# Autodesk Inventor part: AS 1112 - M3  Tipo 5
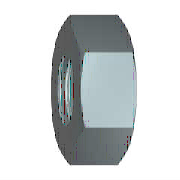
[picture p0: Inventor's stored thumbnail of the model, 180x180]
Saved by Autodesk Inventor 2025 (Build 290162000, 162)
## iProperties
Created: 2024-01
Part Number: AS 1112 - M3  Tipo 5
Material: Acciaio, Dolce
Description: Dadi esagonali metrici ISO, inclusi dadi sottili, dadi con intaglio e dadi a corona
Document SubType Name: Modeling
Standard: AS 1112
Designer: R5800u
Standards Organization: AS
Language: it-IT
Size Designation: M3  Tipo 5
Categories: <MemberInstance><Categories><Category DisplayName="Elementi di fissaggio" InternalName="e4da775c-781d-43d5-af7c-5136215cf5a6" Mnemonic="FSTN"><Category DisplayN
Density: 7.85 g/cm^3
Appearance: Semilucidato
IsCustomPart: 0
Author: R5800u
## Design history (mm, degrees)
workaxis "Work Axis1"
workplane "Work Plane1"
sketch "Schizzo1"
  geometry: L1 (-3.175, 0)-(-1.588, 2.75); L2 (-1.588, 2.75)-(1.588, 2.75); L3 (1.588, 2.75)-(3.175, 0); L4 (3.175, 0)-(1.588, -2.75); L5 (1.588, -2.75)-(-1.588, -2.75); L6 (-1.588, -2.75)-(-3.175, 0); 2 further points
  constraints: 12 end point, 1 coincident, 1 horizontal, 11 other
  dimensions: "d0" = 6.35085 distance of L3.end L1.start (= 1.1547 x SW)
extrude "Corpo" new body sketch "Schizzo1" distance "d1" = 2.4 (= KOH); taper "d2" = 0 deg
revolve "Smusso1" stored, may be unused: angle "d7" = 90 deg
sketch "Schizzo3"
  geometry: A1 r 2.75 centre (0, 0) between (-1.375, -2.382) and (1.375, -2.382) reference; 1 further point
  constraints: 1 coincident
hole "Filettatura" sketch "Schizzo3" diameter "d25" = 2.459; stored, may be unused: countersink angle "d29" = 82 deg, drill point angle "d31" = 118 deg; dims "d26" = 6, "d27" = 4, "d28" = 2, "d30" = 8
body "Solid1"
chamfer "Smusso2" distance "d8" = 0.27063 (= -0.5 x GD1 + 0.5 x NND); stored, may be unused: angle "d9" = 30 deg, second distance "d40" = 0.27063 (= -0.5 x GD1 + 0.5 x NND)
chamfer "Smusso3" distance "d10" = 0.27063 (= -0.5 x GD1 + 0.5 x NND); stored, may be unused: angle "d11" = 30 deg, second distance "d41" = 0.27063 (= -0.5 x GD1 + 0.5 x NND)
sketch "Schizzo2"
  geometry: L1 (0, 1.588)-(0, 3.175) reference; L2 (0, 3.175)-(2.4, 3.175) reference; L3 (2.4, 1.588)-(2.4, 3.175) reference; L4 (-0.48, 0)-(2.88, 0) reference; L5 (0.246, 3.175)-(0, 2.75); L6 (2.154, 3.175)-(2.4, 2.75)
  constraints: 4 end point, 4 point on line
  dimensions: "d3" = 30 deg angle of L1 L5 (= ANG1); "d4" = 30 deg angle of L3 L6 (= ANG2); "d5" = 5.5 diameter of L5.end L4 (= SW0); "d6" = 5.5 diameter of L6.end L4 (= SW01)
other parameters: "ANG1" = 30 deg [user parameter; used in 1 equation term], "ANG2" = 30 deg [user parameter; used in 1 equation term], "NND" = 3 [user parameter; used in 4 equation terms], "KOH" = 2.4 [user parameter; used in 1 equation term], "SW" = 5.5 [user parameter; used in 4 equation terms], "SW0" = 5.5 (= SW) [user parameter; used in 1 equation term], "SW01" = 5.5 (= SW) [user parameter; used in 1 equation term], "GD1" = 2.45873 (computed from THREADDIA, PTC, TOA) [user parameter; used in 4 equation terms], "d13" = 0, "d14" = 0, "d39" = 0, "d42" = 0, "GUL" = 0.27063 (= 0.541266 x PTC) [user parameter], "WFT" = 0.4 [user parameter], "THREADDIA" = 3 [user parameter; used in 1 equation term], "TOA" = 30 deg [user parameter; used in 1 equation term], "PTC" = 0.5 [user parameter; used in 4 equation terms], "E0" = 6.3525 (= 1.155 x SW) [user parameter], "GAL" = 0.27063 (= 0.541266 x PTC) [user parameter]
